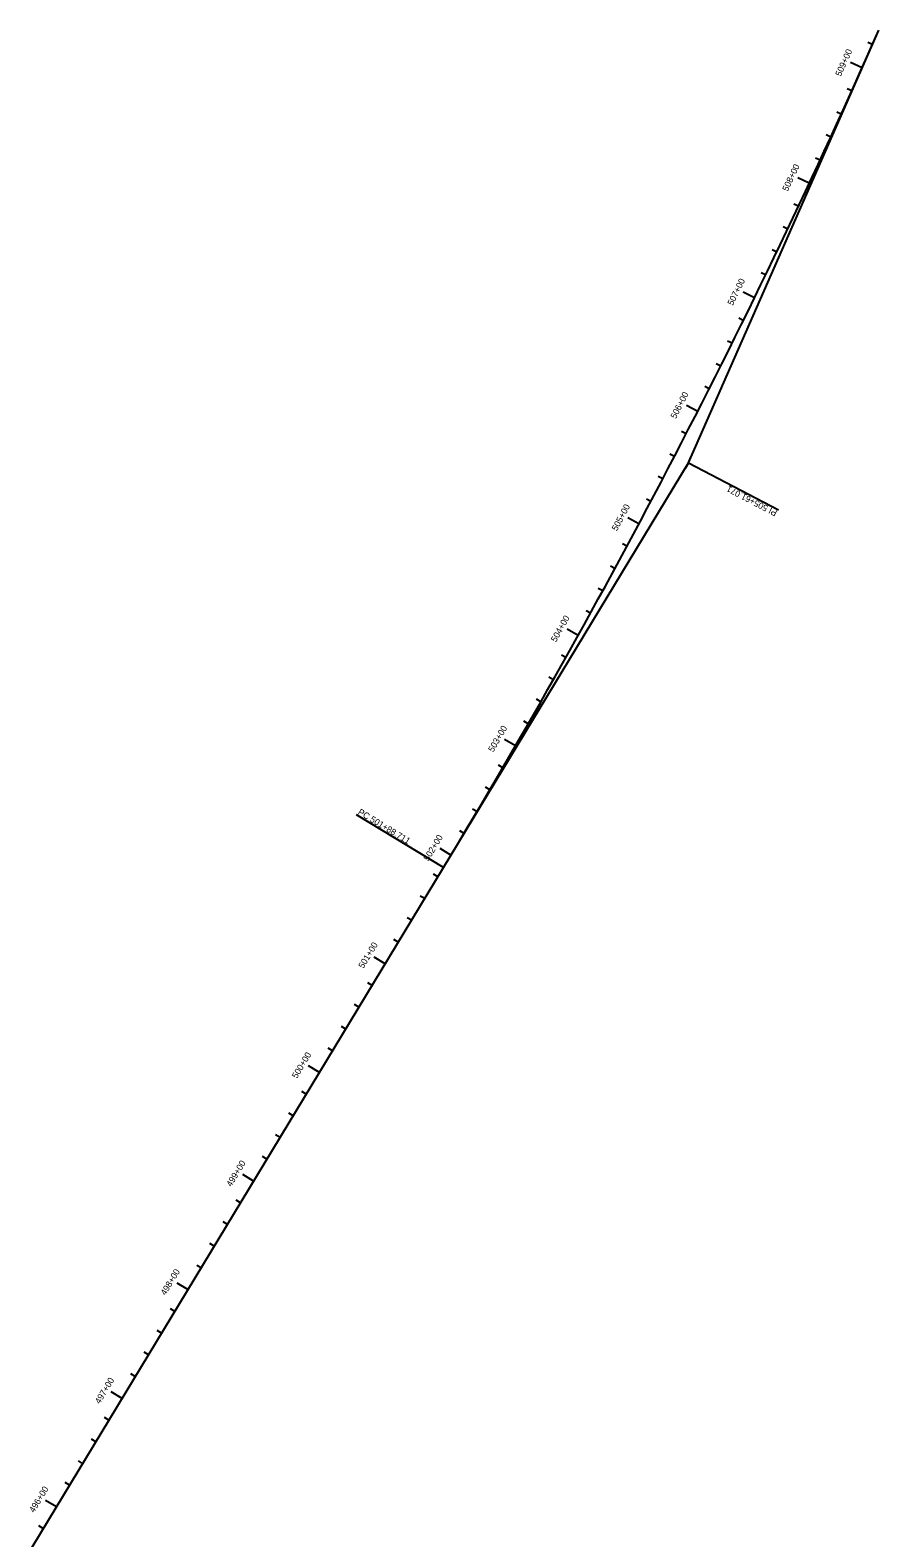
# Model space of a CAD drawing. Extents: x 187748 to 191086, y 249974 to 259749.
# Drawn here: x 189606 to 190275, y 256164 to 257351 of the extents above; entities that cross this region are included whole.
import ezdxf

# ---------------------------------------------------------------- set-up
doc = ezdxf.new("R2010")
doc.units = 0
doc.layers.add('BORDER', color=7, linetype='Continuous')

msp = doc.modelspace()

# ---------------------------------------------------------------- linework, layer by layer
at = {"layer": 'BORDER'}
for p, q in [((190269.7, 257339.9), (190266, 257341.5)), ((190261.6, 257321.6), (190252.4, 257325.7)), ((190253.4, 257303.4), (190249.7, 257305.1)), ((190245.1, 257285.2), (190241.5, 257286.8)), ((190236.8, 257267), (190233.2, 257268.7)), ((190228.4, 257248.8), (190224.8, 257250.5)), ((190219.9, 257230.7), (190210.9, 257235)), ((190211.4, 257212.6), (190207.8, 257214.3)), ((190202.9, 257194.6), (190199.2, 257196.3)), ((190194.2, 257176.5), (190190.6, 257178.3)), ((190185.5, 257158.5), (190181.9, 257160.3)), ((190176.7, 257140.5), (190167.8, 257144.9)), ((190167.9, 257122.6), (190164.3, 257124.4)), ((190159, 257104.7), (190155.4, 257106.5)), ((190150.1, 257086.8), (190146.5, 257088.6)), ((190141, 257068.9), (190137.5, 257070.8)), ((190132, 257051.1), (190123.1, 257055.7)), ((190122.8, 257033.3), (190119.3, 257035.2)), ((190113.6, 257015.6), (190110.1, 257017.4)), ((190124.6, 257010.5), (190126.6, 257015.1)), ((190124.6, 257010.5), (190122, 257006.2)), ((190124.6, 257010.5), (190195.6, 256973.6)), ((190104.4, 256997.9), (190100.8, 256999.7)), ((190095, 256980.2), (190091.5, 256982)), ((190085.6, 256962.5), (190076.8, 256967.2)), ((190076.2, 256944.9), (190072.7, 256946.8)), ((190066.7, 256927.3), (190063.2, 256929.2)), ((190057.1, 256909.7), (190053.6, 256911.6)), ((190047.5, 256892.2), (190044, 256894.1)), ((190037.8, 256874.7), (190029, 256879.6)), ((190028, 256857.2), (190024.5, 256859.2)), ((190018.2, 256839.8), (190014.7, 256841.8)), ((190008.3, 256822.4), (190004.9, 256824.4)), ((189998.4, 256805.1), (189994.9, 256807.1)), ((189988.4, 256787.8), (189979.7, 256792.8)), ((189978.3, 256770.5), (189974.9, 256772.5)), ((189968.2, 256753.2), (189964.8, 256755.2)), ((189931.6, 256692), (189863.2, 256733.5)), ((189958, 256736), (189954.6, 256738)), ((189947.8, 256718.8), (189944.4, 256720.9)), ((189937.5, 256701.7), (189928.9, 256706.8)), ((189607.4, 256156.9), (189931.6, 256692)), ((189927.1, 256684.6), (189923.7, 256686.6)), ((189916.8, 256667.5), (189913.3, 256669.5)), ((189906.4, 256650.4), (189903, 256652.4)), ((189896, 256633.3), (189892.6, 256635.3)), ((189885.7, 256616.1), (189877.1, 256621.3)), ((189875.3, 256599), (189871.9, 256601.1)), ((189864.9, 256581.9), (189861.5, 256584)), ((189854.6, 256564.8), (189851.2, 256566.9)), ((189844.2, 256547.7), (189840.8, 256549.8)), ((189833.9, 256530.6), (189825.3, 256535.8)), ((189823.5, 256513.5), (189820.1, 256515.6)), ((189813.1, 256496.4), (189809.7, 256498.5)), ((189802.8, 256479.3), (189799.3, 256481.4)), ((189792.4, 256462.2), (189789, 256464.3)), ((189782, 256445.1), (189773.5, 256450.3)), ((189771.7, 256428), (189768.3, 256430.1)), ((189761.3, 256410.9), (189757.9, 256413)), ((189750.9, 256393.8), (189747.5, 256395.9)), ((189740.6, 256376.7), (189737.2, 256378.7)), ((189730.2, 256359.6), (189721.7, 256364.7)), ((189719.9, 256342.5), (189716.4, 256344.5)), ((189709.5, 256325.4), (189706.1, 256327.4)), ((189699.1, 256308.3), (189695.7, 256310.3)), ((189688.8, 256291.1), (189685.3, 256293.2)), ((189678.4, 256274), (189669.8, 256279.2)), ((189668, 256256.9), (189664.6, 256259)), ((189657.7, 256239.8), (189654.3, 256241.9)), ((189647.3, 256222.7), (189643.9, 256224.8)), ((189636.9, 256205.6), (189633.5, 256207.7)), ((189626.6, 256188.5), (189618, 256193.7)), ((189616.2, 256171.4), (189612.8, 256173.5))]:
    msp.add_line(p, q, dxfattribs=at)
msp.add_lwpolyline([(189931.6, 256692), (190124.6, 257010.5), (190274.7, 257351.2)], dxfattribs=at)
msp.add_arc((185031.4, 259661), 5729.5, 328.7891, 336.2258, dxfattribs=at)

# ---------------------------------------------------------------- texts
for s, rotation, p in [('509+00', 65.902, (190244.7, 257314.4)), ('508+00', 64.902, (190202.9, 257223.9)), ('507+00', 63.902, (190159.6, 257134)), ('506+00', 62.902, (190114.7, 257044.8)), ('PI 505+61.071', 152.5075, (190195.1, 256972.7)), ('505+00', 61.902, (190068.3, 256956.5)), ('504+00', 60.902, (190020.3, 256869)), ('503+00', 59.902, (189970.8, 256782.4)), ('PC 501+88.711', 328.7891, (189863.7, 256734.3)), ('502+00', 58.902, (189919.8, 256696.6)), ('501+00', 58.7891, (189868.5, 256612)), ('500+00', 58.7891, (189816.1, 256525.4)), ('499+00', 58.7891, (189764.4, 256440.2)), ('498+00', 58.7891, (189712.6, 256354.7)), ('497+00', 58.7891, (189660.8, 256269.2)), ('496+00', 58.7891, (189609, 256183.6))]:
    msp.add_text(s, height=5, rotation=rotation, dxfattribs=at).set_placement(p)

doc.saveas('drawing.dxf')
